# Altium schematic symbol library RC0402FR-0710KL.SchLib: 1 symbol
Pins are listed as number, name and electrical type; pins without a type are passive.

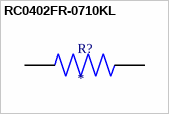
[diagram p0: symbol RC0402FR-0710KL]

## RC0402FR-0710KL
designator R?
10 kOhms Â±1% 0.063W, 1/16W Chip Resistor 0402 (1005 Metric) Moisture Resistant Thick Film; MF: Yageo Corporation; MP: RC0402FR-0710KL
footprint RESC1005X40N
pins: 1, 2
